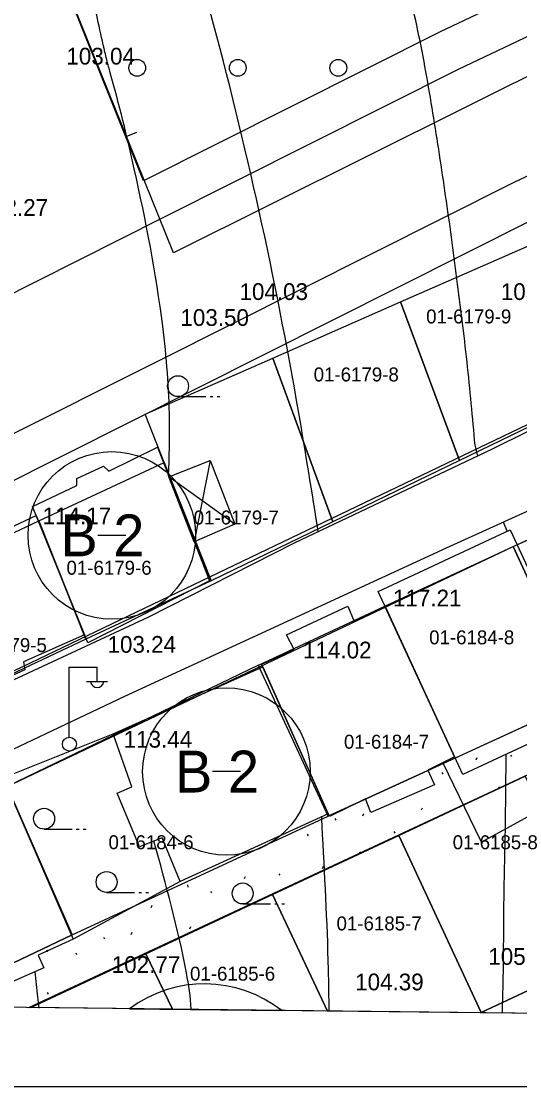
# Model space of a CAD drawing. Extents: x 412225 to 413380, y 4456471 to 4457189.
# Drawn here: x 413137.6 to 413173.3, y 4456471.2 to 4456547.5 of the extents above; entities that cross this region are included whole.
import ezdxf

# ---------------------------------------------------------------- set-up
doc = ezdxf.new("R2010")
doc.units = 0
for name, color, linetype in [('0_HALİHAZIR', 7, 'Continuous'), ('0_KADASTRO', 7, 'Continuous'), ('0_ÇERÇEVE', 7, 'Continuous'), ('Level 27', 7, 'Continuous'), ('Level 28', 7, 'Continuous'), ('Level 31', 7, 'Continuous'), ('Level 32', 7, 'Continuous'), ('Level 41', 7, 'Continuous'), ('Level 43', 7, 'Continuous'), ('Level 57', 7, 'Continuous'), ('Level 62', 7, 'Continuous')]:
    doc.layers.add(name, color=color, linetype=linetype)

msp = doc.modelspace()

# ---------------------------------------------------------------- linework, layer by layer
at = {"layer": '0_HALİHAZIR'}
for p, q in [((413148.846, 4456520.618), (413150.846, 4456520.618)), ((413151.146, 4456520.618), (413151.346, 4456520.618)), ((413151.646, 4456520.618), (413151.846, 4456520.618)), ((413151.138, 4456516.043), (413150.007, 4456510.215)), ((413152.91, 4456511.487), (413148.195, 4456514.877)), ((413172.412, 4456510.983), (413172.159, 4456511.631)), ((413141.052, 4456496.246), (413141.052, 4456501.246)), ((413141.052, 4456501.246), (413143.052, 4456501.246)), ((413143.052, 4456500.246), (413143.052, 4456501.246)), ((413142.292, 4456500.206), (413143.792, 4456500.206)), ((413139.253, 4456489.628), (413141.253, 4456489.628)), ((413141.553, 4456489.628), (413141.753, 4456489.628)), ((413142.053, 4456489.628), (413142.253, 4456489.628)), ((413143.73, 4456485.092), (413145.73, 4456485.092)), ((413146.03, 4456485.092), (413146.23, 4456485.092)), ((413146.53, 4456485.092), (413146.73, 4456485.092)), ((413153.474, 4456484.274), (413155.474, 4456484.274)), ((413155.774, 4456484.274), (413155.974, 4456484.274)), ((413156.274, 4456484.274), (413156.474, 4456484.274))]:
    msp.add_line(p, q, dxfattribs=at)
for points in [[(413238.258, 4456585.176), (413235.202, 4456583.468), (413222.664, 4456576.805), (413209.964, 4456570.118), (413200.027, 4456564.552), (413195.074, 4456561.525), (413194.28, 4456560.779), (413194.219, 4456560.651), (413194.119, 4456559.959), (413196.038, 4456555.43), (413201.969, 4456540.103), (413203.459, 4456535.484), (413204.154, 4456533.714), (413204.389, 4456533.249), (413204.351, 4456532.839), (413194.887, 4456528.424), (413181.477, 4456521.863), (413171.34, 4456516.864), (413157.159, 4456510.114), (413146.72, 4456504.81), (413134.293, 4456499.044), (413130.542, 4456497.258)], [(413203.683, 4456476.074), (413212.46, 4456480.037), (413218.328, 4456483.073), (413218.922, 4456483.486), (413219.449, 4456484.038), (413219.805, 4456484.66), (413219.946, 4456485.18), (413219.975, 4456486.533), (413219.65, 4456487.512), (413214.211, 4456501.344), (413207.789, 4456516.213), (413203.888, 4456524.938), (413203.532, 4456525.318), (413203.064, 4456525.528), (413193.338, 4456521.595), (413178.933, 4456514.71), (413168.044, 4456509.761), (413145.011, 4456499.138), (413133.218, 4456493.547), (413113.393, 4456483.125), (413100.35, 4456477.254)], [(413177.909, 4456497.589), (413179.755, 4456493.714), (413170.585, 4456488.706), (413167.82, 4456494.399)], [(413136.308, 4456493.31), (413144.203, 4456496.449)], [(413148.995, 4456485.875), (413141.322, 4456481.75)]]:
    msp.add_lwpolyline(points, dxfattribs=at)
for points in [[(413138.414, 4456512.754), (413141.592, 4456514.248), (413141.596, 4456514.753), (413143.511, 4456515.634), (413143.893, 4456515.288), (413147.372, 4456516.993), (413151.095, 4456507.414), (413142.383, 4456502.967)], [(413148.195, 4456514.877), (413151.138, 4456516.043), (413152.91, 4456511.487), (413150.007, 4456510.215)], [(413142.145, 4456503.554), (413137.765, 4456501.617), (413137.863, 4456501.043), (413133.268, 4456498.946), (413129.746, 4456507.924), (413138.68, 4456512.097)], [(413172.625, 4456511.083), (413178.712, 4456497.963), (413169.239, 4456493.549), (413163.178, 4456506.668)], [(413168.653, 4456494.817), (413166.746, 4456493.859), (413167.207, 4456492.801), (413162.648, 4456490.832), (413162.271, 4456491.794), (413159.694, 4456490.543), (413154.828, 4456501.443), (413157.164, 4456502.491), (413156.617, 4456503.541), (413160.998, 4456505.614), (413161.45, 4456504.514), (413163.702, 4456505.534)], [(413159.609, 4456490.733), (413148.995, 4456485.875), (413147.705, 4456489.003), (413146.091, 4456488.368), (413144.491, 4456492.218), (413145.538, 4456492.662), (413144.203, 4456496.449), (413154.913, 4456501.252)], [(413136.308, 4456493.31), (413141.322, 4456481.75), (413138.832, 4456480.6), (413139.226, 4456479.681), (413135.096, 4456477.879), (413134.852, 4456478.36), (413132.396, 4456477.279), (413127.104, 4456489.338), (413130.917, 4456491.032), (413131.135, 4456490.559)]]:
    msp.add_lwpolyline(points, close=True, dxfattribs=at)
for centre, radius in [((413148.846, 4456521.368), 0.75), ((413141.062, 4456495.721), 0.5), ((413139.253, 4456490.378), 0.75), ((413143.73, 4456485.842), 0.75), ((413153.474, 4456485.024), 0.75)]:
    msp.add_circle(centre, radius, dxfattribs=at)
msp.add_arc((413143.052, 4456500.249), 0.474, 184.83843, 355.14641, dxfattribs=at)
for points in [[(413158.891, 4456510.938), (413157.497, 4456519.429), (413141.887, 4456576.329), (413138.743, 4456582.795), (413135.772, 4456586.346)], [(413170.12, 4456517.133), (413169.85, 4456520.12), (413169.546, 4456523.104), (413169.197, 4456526.084), (413168.825, 4456529.061), (413168.431, 4456532.035), (413168.012, 4456535.005), (413167.57, 4456537.972), (413167.103, 4456540.936), (413166.597, 4456543.893), (413166.027, 4456546.837), (413165.368, 4456549.762), (413164.609, 4456552.663), (413163.76, 4456555.539), (413162.821, 4456558.387), (413161.776, 4456561.197), (413160.595, 4456563.951), (413159.251, 4456566.627), (413157.752, 4456569.222), (413156.125, 4456571.74), (413154.452, 4456574.23), (413152.836, 4456576.753), (413151.336, 4456579.346), (413149.937, 4456582), (413148.572, 4456584.671), (413147.786, 4456586.209)], [(413183.716, 4456522.959), (413183.746, 4456523.408), (413183.475, 4456526.454), (413178.14, 4456541.977), (413177.37, 4456544.327), (413177.094, 4456545.269), (413176.874, 4456545.838), (413166.252, 4456566.919), (413162.411, 4456573.904), (413159.59, 4456578.934), (413155.895, 4456586.116)], [(413196.096, 4456528.988), (413196.087, 4456529.027), (413195.748, 4456530.021), (413193.504, 4456533.949), (413188.263, 4456543.561), (413185.689, 4456548.185), (413180.408, 4456557.254), (413174.689, 4456566.541), (413168.028, 4456577.107), (413166.263, 4456580.161), (413163.275, 4456586.032)], [(413202.235, 4456539.277), (413201.769, 4456539.8), (413201.203, 4456540.712), (413194.038, 4456553.687), (413192.376, 4456556.283), (413186.602, 4456563.99), (413186.157, 4456564.519), (413186.068, 4456564.621), (413185.671, 4456565.074), (413184.836, 4456565.991), (413183.656, 4456567.306), (413181.257, 4456570.178), (413173.574, 4456580.267), (413172.858, 4456581.365), (413171.115, 4456584.499), (413170.309, 4456585.951)], [(413148.171, 4456514.938), (413148.235, 4456518.974), (413147.746, 4456525.665), (413145.705, 4456536.938), (413143.992, 4456543.827), (413143.872, 4456544.26), (413143.608, 4456545.312), (413142.684, 4456549.524), (413139.71, 4456563.253)], [(413170.319, 4456516.378), (413170.303, 4456516.438), (413170.12, 4456517.133)], [(413172.074, 4456476.435), (413172.105, 4456477.544), (413172.161, 4456480.54), (413172.18, 4456483.539), (413172.23, 4456486.538), (413172.289, 4456489.537), (413172.326, 4456492.537), (413172.344, 4456494.996)], [(413159.668, 4456476.577), (413159.619, 4456479.58), (413159.167, 4456489.854), (413159.132, 4456490.515)], [(413149.785, 4456476.69), (413149.783, 4456476.742), (413149.445, 4456479.333), (413147.119, 4456488.772)], [(413138.899, 4456476.814), (413138.813, 4456477.602), (413138.614, 4456479.414)]]:
    msp.add_spline(points, degree=3, dxfattribs=at)
at = {"layer": '0_KADASTRO'}
for p, q in [((413154.609, 4456501.372), (413144.276, 4456496.388)), ((413154.735, 4456501.1), (413154.609, 4456501.372)), ((413159.591, 4456490.571), (413154.735, 4456501.1)), ((413141.262, 4456482.055), (413159.591, 4456490.571))]:
    msp.add_line(p, q, dxfattribs=at)
for points in [[(413139.67, 4456552.89), (413181.44, 4456573.73), (413190.36, 4456551.8), (413148.51, 4456530.92)], [(413164.789, 4456527.405), (413173.942, 4456531.432), (413177.882, 4456520.339), (413168.999, 4456516.038)], [(413155.636, 4456523.379), (413164.789, 4456527.405), (413168.999, 4456516.038), (413159.926, 4456511.645)], [(413146.482, 4456519.352), (413155.636, 4456523.379), (413159.926, 4456511.645), (413151.214, 4456507.426), (413147.849, 4456515.907)], [(413138.87, 4456511.712), (413147.849, 4456515.907), (413151.214, 4456507.426), (413142.235, 4456503.231)], [(413172.844, 4456509.878), (413182.113, 4456514.107), (413182.282, 4456513.71), (413186.551, 4456503.67), (413186.864, 4456502.933), (413188.06, 4456500.13), (413181.865, 4456497.232), (413179.239, 4456496.003), (413177.878, 4456498.951)], [(413129.968, 4456507.514), (413138.87, 4456511.712), (413142.235, 4456503.231), (413133.333, 4456499.033)], [(413163.657, 4456505.607), (413172.844, 4456509.878), (413177.878, 4456498.951), (413168.684, 4456494.72)], [(413154.609, 4456501.372), (413163.657, 4456505.607), (413168.684, 4456494.72), (413168.134, 4456494.469), (413159.591, 4456490.571), (413154.735, 4456501.1)], [(413164.656, 4456489.179), (413169.579, 4456491.483), (413173.714, 4456493.417), (413174.894, 4456490.839), (413179.538, 4456480.696), (413170.554, 4456476.492)], [(413127.619, 4456488.3), (413136.611, 4456492.691), (413141.262, 4456482.055), (413132.227, 4456477.758), (413131.854, 4456478.609)]]:
    msp.add_lwpolyline(points, close=True, dxfattribs=at)
for points in [[(413144.276, 4456496.388), (413136.611, 4456492.691), (413141.262, 4456482.055)], [(413159.539, 4456476.598), (413155.599, 4456484.94), (413164.656, 4456489.179), (413170.554, 4456476.492), (413170.51, 4456476.472)], [(413148.448, 4456476.727), (413146.542, 4456480.702), (413155.599, 4456484.94), (413159.539, 4456476.598)], [(413138.296, 4456476.844), (413146.542, 4456480.702), (413148.448, 4456476.727)], [(413170.564, 4456476.471), (413170.554, 4456476.492), (413179.538, 4456480.696), (413181.531, 4456476.344)], [(413148.448, 4456476.727), (413138.296, 4456476.844)], [(413159.539, 4456476.598), (413148.448, 4456476.727)], [(413170.51, 4456476.472), (413159.539, 4456476.598)], [(413170.51, 4456476.472), (413170.554, 4456476.492), (413170.564, 4456476.471)], [(413170.564, 4456476.471), (413170.51, 4456476.472)], [(413181.531, 4456476.344), (413170.564, 4456476.471)]]:
    msp.add_lwpolyline(points, dxfattribs=at)
at = {"layer": '0_ÇERÇEVE'}
for points in [[(412231.94, 4457188.937), (413313.937, 4457188.937), (413313.937, 4456471.176), (412231.94, 4456471.176)], [(412246.74, 4457181.275), (413310.435, 4457168.98), (413302.463, 4456474.947), (412238.67, 4456487.241)]]:
    msp.add_lwpolyline(points, close=True, dxfattribs=at)
at = {"layer": 'Level 27'}
for p, q in [((413199.778, 4456531.047), (413093.013, 4456479.834)), ((413172.844, 4456509.878), (413203.89, 4456523.726)), ((413136.611, 4456492.691), (413172.844, 4456509.878))]:
    msp.add_line(p, q, dxfattribs=at)
at = {"layer": 'Level 28'}
for p, q in [((413146.371, 4456536.083), (413106.294, 4456635.724)), ((413248.489, 4456585.195), (413167.617, 4456546.757)), ((413167.617, 4456546.757), (413146.371, 4456536.083)), ((413088.907, 4456490.425), (413174.204, 4456533.28))]:
    msp.add_line(p, q, dxfattribs=at)
msp.add_lwpolyline([(413145.867, 4456539.542), (413145.1, 4456539.243)], dxfattribs=at)
at = {"layer": 'Level 31'}
msp.add_lwpolyline([(413145.366, 4456476.762), (413156.276, 4456476.636)], dxfattribs=at)
msp.add_arc((413150.738, 4456469.541), 9, 52.02668, 126.64903, dxfattribs=at)
at = {"layer": 'Level 32'}
for p, q in [((413145.099, 4456510.676), (413143.099, 4456510.676)), ((413153.309, 4456493.753), (413151.309, 4456493.753))]:
    msp.add_line(p, q, dxfattribs=at)
for centre in [(413144.099, 4456510.677), (413152.309, 4456493.754)]:
    msp.add_circle(centre, 6, dxfattribs=at)
at = {"layer": 'Level 41'}
for p, q in [((413170.187, 4456494.593), (413170.259, 4456494.753)), ((413172.652, 4456494.938), (413172.723, 4456494.831)), ((413167.747, 4456493.677), (413167.817, 4456493.57)), ((413171.815, 4456492.56), (413171.875, 4456492.693)), ((413162.072, 4456490.595), (413162.143, 4456490.755)), ((413166.282, 4456491.003), (413166.352, 4456491.163)), ((413160.084, 4456490.387), (413160.155, 4456490.281)), ((413158.098, 4456489.266), (413158.169, 4456489.159)), ((413164.292, 4456489.458), (413164.363, 4456489.351)), ((413161.836, 4456488.005), (413161.888, 4456487.926)), ((413159.195, 4456486.812), (413159.266, 4456486.971)), ((413153.601, 4456486.083), (413153.673, 4456486.243)), ((413156.066, 4456486.428), (413156.137, 4456486.321)), ((413149.531, 4456485.637), (413149.549, 4456485.477)), ((413151.161, 4456485.167), (413151.231, 4456485.06)), ((413146.924, 4456484.023), (413146.996, 4456484.183)), ((413145.486, 4456482.085), (413145.557, 4456482.245)), ((413149.696, 4456482.493), (413149.766, 4456482.653)), ((413143.498, 4456481.877), (413143.569, 4456481.771)), ((413139.413, 4456480.948), (413139.484, 4456480.841)), ((413141.512, 4456480.756), (413141.583, 4456480.649)), ((413139.48, 4456477.918), (413139.551, 4456477.811))]:
    msp.add_line(p, q, dxfattribs=at)
at = {"layer": 'Level 43'}
for centre in [(413145.923, 4456544.179), (413153.123, 4456544.179), (413160.323, 4456544.179)]:
    msp.add_circle(centre, 0.6, dxfattribs=at)
at = {"layer": 'Level 57'}
msp.add_line((413138.149, 4456476.846), (413209.462, 4456510.132), dxfattribs=at)
msp.add_lwpolyline([(413130.494, 4456476.934), (413132.227, 4456477.758), (413141.262, 4456482.055), (413159.591, 4456490.571), (413177.878, 4456498.951), (413186.864, 4456502.933), (413195.021, 4456506.702), (413203.385, 4456510.567), (413208.344, 4456512.858)], dxfattribs=at)
at = {"layer": 'Level 62'}
for p, q in [((413189.644, 4456553.905), (413168.904, 4456544.048)), ((413168.963, 4456544.077), (413147.718, 4456533.402)), ((413172.916, 4456535.99), (413190.383, 4456544.291)), ((413147.492, 4456523.217), (413172.916, 4456535.99)), ((413147.718, 4456533.402), (413138.763, 4456528.903)), ((413138.763, 4456528.903), (413086.081, 4456502.18)), ((413057.063, 4456477.783), (413147.492, 4456523.217))]:
    msp.add_line(p, q, dxfattribs=at)

# ---------------------------------------------------------------- texts
at = {"layer": '0_HALİHAZIR'}
for s, p in [('103.04 ', (413140.848, 4456544.413)), ('102.27', (413134.631, 4456533.571)), ('104.03', (413153.246, 4456527.543)), ('105.41', (413171.963, 4456527.543)), ('103.50', (413149.015, 4456525.688)), ('114.17', (413139.145, 4456511.474)), ('117.21', (413164.237, 4456505.587)), ('103.24 ', (413143.794, 4456502.267)), ('114.02', (413157.797, 4456501.862)), ('113.44', (413144.95, 4456495.468)), ('105.17 ', (413171.069, 4456479.908)), ('102.77 ', (413144.098, 4456479.326)), ('104.39', (413161.53, 4456478.08))]:
    msp.add_text(s, height=1.2, dxfattribs=at).set_placement(p)
at = {"layer": '0_KADASTRO'}
for s, p in [('01-6179-9', (413166.617, 4456525.864)), ('01-6179-9', (413166.617, 4456525.864)), ('01-6179-8', (413158.559, 4456521.709)), ('01-6179-8', (413158.559, 4456521.709)), ('01-6179-7', (413149.965, 4456511.459)), ('01-6179-7', (413149.965, 4456511.459)), ('01-6179-6', (413140.855, 4456507.858)), ('01-6179-6', (413140.855, 4456507.858)), ('01-6184-8', (413166.832, 4456502.872)), ('01-6184-8', (413166.832, 4456502.872)), ('01-6179-5', (413133.352, 4456502.318)), ('01-6179-5', (413133.352, 4456502.318)), ('01-6184-7', (413160.729, 4456495.393)), ('01-6184-7', (413160.729, 4456495.393)), ('01-6184-6', (413143.863, 4456488.191)), ('01-6184-6', (413143.863, 4456488.191)), ('01-6185-8', (413168.517, 4456488.191)), ('01-6185-8', (413168.517, 4456488.191)), ('01-6185-7', (413160.198, 4456482.374)), ('01-6185-7', (413160.198, 4456482.374)), ('01-6185-6', (413149.703, 4456478.773)), ('01-6185-6', (413149.703, 4456478.773))]:
    msp.add_text(s, height=1, dxfattribs=at).set_placement(p)
at = {"layer": 'Level 32'}
for p in [(413140.417, 4456509.178), (413148.627, 4456492.255)]:
    msp.add_text('B 2', height=3, dxfattribs=at).set_placement(p)

doc.saveas('drawing.dxf')
